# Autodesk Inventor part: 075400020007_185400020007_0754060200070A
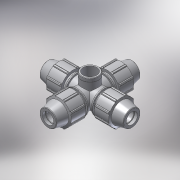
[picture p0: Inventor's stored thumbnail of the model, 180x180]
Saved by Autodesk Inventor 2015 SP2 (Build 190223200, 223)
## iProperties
Created: 2017-02
Part Number: 075400020007_185400020007_0754060200070A
Material: PVC-Piping
Description: CROSS WITH FEMALE ADAPTOR 20-20-20-20-3/4"
Document SubType Name: Modeling
Designer: KIM
Mass: 92.6774 g
Surface Area: 199.44 cm^2
Volume: 66.1981 cm^3
Density: 1.4 g/cm^3
Appearance: Smooth - White
Author: Кирилл
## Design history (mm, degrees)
derived "07540.ipt"
feature "Solid1::07540.ipt"
feature "Solid2::07540.ipt"
tag "TaggingFeature1"
body "Solid1"
other parameters: "d4" = 6.20833, "d5" = 17.88, "d7" = 48, "d11" = 2.48333, "d13" = 120 deg, "d15" = 12 deg, "d16" = 41.76, "d18" = 1, "d19" = 35 deg, "d20" = 17.5 deg, "d21" = 44.64, "d23" = 0, "d25" = 360 deg, "d27" = 0.96, "d33" = 0.4, "d42" = 26.82, "d43" = 1.44, "d46" = 0.6, "d68" = 4.47, "d72" = 35, "d76" = 24.117, "d80" = 0.72351, "d91" = 36, "d93" = 57, "d95" = 18, "d112" = 21, "d116" = 135 deg, "d117" = 27.73455, "d118" = 149, "d119" = 18, "d121" = 0, "d122" = 12.6, "d124" = 0, "d128" = 0, "d129" = 2, "d130" = 6.3, "d131" = 0.3, "d132" = 0.3, "d133" = 30.14625, "d135" = 90 deg, "d138" = 0, "d140" = 90 deg, "d143" = 0, "d144" = 18, "d146" = 0, "d147" = 18, "d149" = 0, "d151" = 0, "d154" = 21, "d155" = 0, "d156" = 19.2936, "d159" = 0, "E_" = 48, "A_" = 35, "l_" = 57, "l_2" = 21, "Rp_" = 24.117, "H_" = 149, "d157" = 24.117
